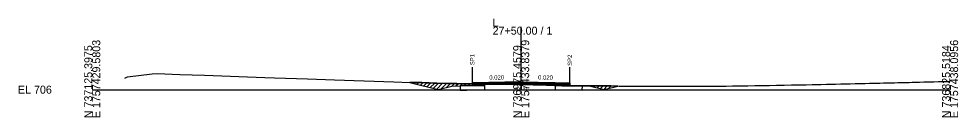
# Model space of a CAD drawing. Extents: x -26 to 4303, y -10 to 9577.
# Drawn here: x 974.3 to 1302.8, y 7490.3 to 7524.9 of the extents above; entities that cross this region are included whole.
import ezdxf

# ---------------------------------------------------------------- set-up
doc = ezdxf.new("R2010")
doc.units = 0
for name, color, linetype in [('Exist CMT Pavement', 7, 'Continuous'), ('Old_Level_2', 7, 'Continuous'), ('Pattern 1', 7, 'Continuous'), ('Prop CMT Conc Surface', 7, 'Continuous'), ('Prop CMT Concrete Structures', 7, 'Continuous'), ('Prop CMT Pvmt Course 1', 7, 'Continuous'), ('Prop CMT Pvmt Course 1 CG', 7, 'Continuous'), ('Prop CMT Pvmt Course 1 Wedge', 7, 'Continuous'), ('Prop CMT Pvmt Surface', 7, 'Continuous'), ('Prop CMT Pvmt Surface Shoulder', 7, 'Continuous'), ('Prop CMT Pvmt Wedge Surface 1', 7, 'Continuous'), ('Prop CMT Pvmt Wedge Surface 2', 7, 'Continuous'), ('Prop CMT Pvmt Wedge Surface 3', 7, 'Continuous'), ('Prop CMT Shld Paved Course 1', 7, 'Continuous'), ('Prop CMT Shld Paved Course 3', 7, 'Continuous'), ('Prop CMT Slope Grass', 7, 'Continuous'), ('Prop Road Sect_ Recs - UC Shallow (Outline)', 7, 'Continuous'), ('Prop Shade Light', 7, 'Continuous'), ('Prop XS DDE Elevations', 7, 'Continuous'), ('Prop XS SE Text', 7, 'Continuous'), ('Prop XS Shear Point Label', 7, 'Continuous'), ('Prop XS Wedging', 7, 'Continuous')]:
    doc.layers.add(name, color=color, linetype=linetype)

msp = doc.modelspace()

# ---------------------------------------------------------------- linework, layer by layer
at = {"layer": 'Exist CMT Pavement'}
for p, q in [((1133, 7502.37), (1133, 7502.03)), ((1167, 7502.37), (1167, 7501.36))]:
    msp.add_line(p, q, dxfattribs=at)
for points in [[(1150, 7502.71), (1133, 7502.37)], [(1150, 7502.71), (1167, 7502.37)]]:
    msp.add_lwpolyline(points, dxfattribs=at)
at = {"layer": 'Old_Level_2'}
for p, q in [((1150, 7500), (1150, 7522.1)), ((1150, 7500), (1150, 7522.1)), ((1000, 7500), (1150, 7500)), ((1000, 7500), (1150, 7500)), ((1150, 7500), (1300, 7500)), ((1150, 7500), (1300, 7500))]:
    msp.add_line(p, q, dxfattribs=at)
at = {"layer": 'Pattern 1'}
for p, q in [((1111.41, 7502.47), (1111.48, 7502.54)), ((1112.54, 7502.19), (1112.86, 7502.51)), ((1113.67, 7501.91), (1114.25, 7502.48)), ((1114.81, 7501.63), (1115.63, 7502.45)), ((1115.94, 7501.34), (1117, 7502.41)), ((1117.07, 7501.06), (1118.38, 7502.37)), ((1118.2, 7500.78), (1119.75, 7502.33)), ((1119.33, 7500.49), (1121.13, 7502.29)), ((1120.46, 7500.21), (1122.51, 7502.25)), ((1121.99, 7500.32), (1123.88, 7502.22)), ((1123.87, 7500.8), (1125.26, 7502.19)), ((1125.75, 7501.26), (1126.65, 7502.16)), ((1127.19, 7501.29), (1128.03, 7502.12)), ((1128.64, 7501.32), (1129.41, 7502.09)), ((1130.08, 7501.34), (1130.79, 7502.06)), ((1131.52, 7501.37), (1132.18, 7502.03)), ((1132.97, 7501.4), (1133.59, 7502.02)), ((1134.41, 7501.43), (1134.97, 7501.99)), ((1135.85, 7501.46), (1136.35, 7501.95)), ((1171.59, 7501.32), (1171.6, 7501.33)), ((1172.97, 7501.29), (1173, 7501.32)), ((1174.34, 7501.24), (1174.41, 7501.31)), ((1175.47, 7500.96), (1175.81, 7501.3)), ((1176.6, 7500.68), (1177.22, 7501.29)), ((1177.73, 7500.39), (1178.63, 7501.29)), ((1178.87, 7500.11), (1180.05, 7501.29)), ((1180.66, 7500.49), (1181.46, 7501.3)), ((1182.55, 7500.96), (1182.87, 7501.29))]:
    msp.add_line(p, q, dxfattribs=at)
for points in [[(1121, 7500.08), (1125.72, 7501.26), (1128.61, 7501.31), (1137.25, 7501.49), (1137.25, 7501.94), (1136.11, 7501.96), (1135, 7501.99), (1134.01, 7502.02), (1131.95, 7502.04), (1130.44, 7502.06), (1129.08, 7502.09), (1127.46, 7502.14), (1125.02, 7502.19), (1120.46, 7502.31), (1115.23, 7502.46), (1111.11, 7502.55)], [(1179, 7500.08), (1183.82, 7501.28), (1181.36, 7501.3), (1177.96, 7501.29), (1175.34, 7501.31), (1174.06, 7501.31), (1171.39, 7501.33), (1174.28, 7501.26)]]:
    msp.add_lwpolyline(points, close=True, dxfattribs=at)
at = {"layer": 'Prop CMT Conc Surface'}
for points in [[(1137.08, 7502.2), (1133, 7502.12)], [(1133, 7502.12), (1133, 7501.91)], [(1133, 7501.91), (1137.08, 7501.99)], [(1137.08, 7501.99), (1137.08, 7502.2)], [(1161.94, 7502.01), (1161.94, 7502.22)], [(1161.94, 7502.22), (1167, 7502.12)], [(1167, 7501.91), (1161.94, 7502.01)], [(1167, 7502.12), (1167, 7501.91)]]:
    msp.add_lwpolyline(points, dxfattribs=at)
at = {"layer": 'Prop CMT Concrete Structures'}
for points in [[(1133, 7502.12), (1133, 7502.37)], [(1137.08, 7502.2), (1133, 7502.12)], [(1150, 7502.59), (1137.08, 7502.33)], [(1137.08, 7502.33), (1137.08, 7502.2)], [(1150, 7502.59), (1161.94, 7502.35)], [(1161.94, 7502.35), (1161.94, 7502.22)], [(1161.94, 7502.22), (1167, 7502.12)], [(1167, 7502.12), (1167, 7502.37)]]:
    msp.add_lwpolyline(points, dxfattribs=at)
at = {"layer": 'Prop CMT Pvmt Course 1'}
for points in [[(1137.08, 7501.99), (1133, 7501.91)], [(1133, 7501.91), (1133, 7501.58)], [(1133, 7501.58), (1137.08, 7501.66)], [(1137.08, 7501.66), (1137.08, 7501.99)], [(1161.94, 7502.01), (1167, 7501.91)], [(1161.94, 7501.55), (1161.94, 7502.01)], [(1167, 7501.58), (1161.94, 7501.68)], [(1167, 7501.91), (1167, 7501.58)]]:
    msp.add_lwpolyline(points, dxfattribs=at)
at = {"layer": 'Prop CMT Pvmt Course 1 Wedge'}
for points in [[(1137.08, 7501.99), (1139.2, 7502.03), (1139.42, 7502.04), (1141.7, 7502.08), (1141.85, 7502.09), (1144.21, 7502.13), (1144.28, 7502.14), (1146.71, 7502.18), (1146.71, 7502.18), (1146.9, 7502.19), (1149.14, 7502.23), (1149.21, 7502.23), (1150, 7502.25)], [(1137.08, 7501.93), (1137.08, 7501.99)], [(1150, 7501.83), (1149.21, 7501.86), (1149.14, 7501.86), (1146.9, 7501.89), (1146.71, 7501.89), (1146.71, 7501.89), (1144.28, 7501.91), (1144.21, 7501.91), (1141.85, 7501.95), (1141.7, 7501.95), (1139.42, 7501.98), (1139.2, 7501.98), (1137.08, 7501.93)], [(1150, 7502.25), (1150, 7501.83)], [(1150, 7502.25), (1151.58, 7502.22), (1151.71, 7502.22), (1154.01, 7502.17), (1154.21, 7502.17), (1156.44, 7502.12), (1156.71, 7502.12), (1158.87, 7502.07), (1159.21, 7502.07), (1159.57, 7502.06), (1161.71, 7502.02), (1161.94, 7502.01)], [(1161.94, 7501.51), (1161.71, 7501.52), (1159.57, 7501.56), (1159.21, 7501.57), (1158.87, 7501.59), (1156.71, 7501.67), (1156.44, 7501.67), (1154.21, 7501.74), (1154.01, 7501.74), (1151.71, 7501.77), (1151.58, 7501.78), (1150, 7501.83)], [(1161.94, 7502.01), (1161.94, 7501.51)]]:
    msp.add_lwpolyline(points, dxfattribs=at)
at = {"layer": 'Prop CMT Pvmt Surface'}
for points in [[(1150, 7502.46), (1133, 7502.12)], [(1133, 7502.12), (1133, 7502.37)], [(1150, 7502.46), (1167, 7502.12)], [(1167, 7502.12), (1167, 7502.37)]]:
    msp.add_lwpolyline(points, dxfattribs=at)
at = {"layer": 'Prop CMT Pvmt Surface Shoulder'}
msp.add_line((1150, 7501.83), (1157.28, 7501.65), dxfattribs=at)
for points in [[(1137.09, 7501.93), (1139.2, 7501.98), (1139.42, 7501.98), (1141.7, 7501.95), (1141.85, 7501.95), (1144.21, 7501.91), (1144.28, 7501.91), (1146.71, 7501.89), (1146.71, 7501.89), (1146.9, 7501.89), (1149.14, 7501.86), (1149.21, 7501.86), (1150, 7501.83)], [(1157.28, 7501.65), (1158.87, 7501.59), (1159.21, 7501.57), (1159.57, 7501.56), (1161.71, 7501.52), (1161.94, 7501.51)]]:
    msp.add_lwpolyline(points, dxfattribs=at)
at = {"layer": 'Prop CMT Pvmt Wedge Surface 1'}
for p, q in [((1133, 7501.45), (1133, 7502.03)), ((1137.08, 7501.53), (1133, 7501.45)), ((1161.94, 7501.55), (1167, 7501.45)), ((1167, 7501.58), (1167, 7501.45))]:
    msp.add_line(p, q, dxfattribs=at)
for points in [[(1137.08, 7501.53), (1137.09, 7501.94)], [(1161.94, 7501.55), (1161.94, 7501.51)]]:
    msp.add_lwpolyline(points, dxfattribs=at)
at = {"layer": 'Prop CMT Pvmt Wedge Surface 2'}
for points in [[(1137.08, 7502.33), (1139.2, 7502.37), (1139.42, 7502.37), (1141.7, 7502.42), (1141.85, 7502.42), (1144.21, 7502.47), (1144.28, 7502.47), (1146.71, 7502.52), (1146.71, 7502.52), (1146.9, 7502.52), (1149.14, 7502.57), (1149.21, 7502.57), (1150, 7502.59)], [(1150, 7502.46), (1149.21, 7502.44), (1149.14, 7502.44), (1146.9, 7502.4), (1146.71, 7502.39), (1146.71, 7502.39), (1144.28, 7502.35), (1144.21, 7502.34), (1141.85, 7502.3), (1141.7, 7502.29), (1139.42, 7502.25), (1139.2, 7502.24), (1137.08, 7502.2)], [(1137.08, 7501.94), (1137.08, 7502.33)], [(1150, 7502.59), (1150, 7502.46)], [(1150, 7502.59), (1151.58, 7502.55), (1151.71, 7502.55), (1154.01, 7502.5), (1154.21, 7502.5), (1156.44, 7502.46), (1156.71, 7502.45), (1158.87, 7502.41), (1159.21, 7502.4), (1159.57, 7502.39), (1161.71, 7502.35), (1161.94, 7502.35)], [(1161.94, 7502.22), (1161.71, 7502.23), (1159.57, 7502.27), (1159.21, 7502.28), (1158.87, 7502.28), (1156.71, 7502.33), (1156.44, 7502.33), (1154.21, 7502.38), (1154.01, 7502.38), (1151.71, 7502.43), (1151.58, 7502.43), (1150, 7502.46)], [(1161.94, 7502.35), (1161.94, 7501.51)]]:
    msp.add_lwpolyline(points, dxfattribs=at)
at = {"layer": 'Prop CMT Pvmt Wedge Surface 3'}
for points in [[(1137.08, 7502.2), (1139.2, 7502.24), (1139.42, 7502.25), (1141.7, 7502.29), (1141.85, 7502.3), (1144.21, 7502.34), (1144.28, 7502.35), (1146.71, 7502.39), (1146.71, 7502.39), (1146.9, 7502.4), (1149.14, 7502.44), (1149.21, 7502.44), (1150, 7502.46)], [(1150, 7502.25), (1149.21, 7502.24), (1149.14, 7502.23), (1146.9, 7502.19), (1146.71, 7502.19), (1146.71, 7502.19), (1144.28, 7502.14), (1144.21, 7502.14), (1141.85, 7502.09), (1141.7, 7502.09), (1139.42, 7502.04), (1139.2, 7502.04), (1137.08, 7501.99)], [(1137.08, 7501.99), (1137.08, 7502.2)], [(1150, 7502.46), (1150, 7502.25)], [(1150, 7502.46), (1151.58, 7502.43), (1151.71, 7502.43), (1154.01, 7502.38), (1154.21, 7502.38), (1156.44, 7502.33), (1156.71, 7502.33), (1158.87, 7502.28), (1159.21, 7502.28), (1159.57, 7502.27), (1161.71, 7502.23), (1161.94, 7502.22)], [(1161.94, 7502.01), (1161.71, 7502.02), (1159.57, 7502.06), (1159.21, 7502.07), (1158.87, 7502.07), (1156.71, 7502.12), (1156.44, 7502.12), (1154.21, 7502.17), (1154.01, 7502.17), (1151.71, 7502.22), (1151.58, 7502.22), (1150, 7502.25)], [(1161.94, 7502.22), (1161.94, 7502.01)]]:
    msp.add_lwpolyline(points, dxfattribs=at)
at = {"layer": 'Prop CMT Shld Paved Course 1'}
for points in [[(1133, 7501.91), (1133, 7502.37)], [(1150, 7502.25), (1133, 7501.91)], [(1150, 7502.25), (1167, 7501.91)], [(1167, 7501.91), (1167, 7502.37)]]:
    msp.add_lwpolyline(points, dxfattribs=at)
at = {"layer": 'Prop CMT Shld Paved Course 3'}
for points in [[(1150, 7502.71), (1133, 7502.37)], [(1133, 7502.37), (1133, 7502.12)], [(1133, 7502.12), (1137.08, 7502.2)], [(1137.08, 7502.33), (1150, 7502.59)], [(1137.08, 7502.2), (1137.08, 7502.33)], [(1150, 7502.71), (1167, 7502.37)], [(1161.94, 7502.35), (1150, 7502.59)], [(1161.94, 7502.22), (1161.94, 7502.35)], [(1167, 7502.12), (1161.94, 7502.22)], [(1167, 7502.37), (1167, 7502.12)]]:
    msp.add_lwpolyline(points, dxfattribs=at)
at = {"layer": 'Prop CMT Slope Grass'}
msp.add_lwpolyline([(1011.35, 7504.04), (1012.37, 7504.5), (1020.98, 7505.54), (1022.65, 7505.65), (1030.67, 7505.36), (1039.2, 7505.06), (1060.32, 7504.3), (1063.69, 7504.18), (1075.33, 7503.79), (1084.67, 7503.45), (1105.5, 7502.75), (1111.17, 7502.55), (1114.7, 7502.48), (1116.69, 7502.41), (1117.53, 7502.39), (1119.2, 7502.34), (1119.96, 7502.32), (1121.7, 7502.27), (1122.39, 7502.26), (1124.2, 7502.21), (1126.11, 7502.17), (1126.7, 7502.16), (1127.26, 7502.15), (1129.2, 7502.09), (1131.26, 7502.05), (1131.7, 7502.04), (1132.12, 7502.04), (1134.2, 7502.02), (1134.55, 7502.01), (1136.98, 7501.93), (1139.2, 7501.98), (1141.85, 7501.95), (1144.28, 7501.91), (1146.9, 7501.89), (1149.21, 7501.86), (1150, 7501.83), (1151.71, 7501.77), (1154.21, 7501.74), (1156.71, 7501.67), (1158.87, 7501.59), (1159.21, 7501.57), (1159.57, 7501.56), (1161.71, 7501.52), (1162.15, 7501.5), (1164.21, 7501.36), (1164.72, 7501.36), (1166.71, 7501.36), (1167.29, 7501.35), (1169.22, 7501.34), (1169.87, 7501.34), (1171.72, 7501.32), (1172.44, 7501.32), (1174.22, 7501.31), (1175.02, 7501.31), (1176.72, 7501.29), (1177.59, 7501.29), (1179.22, 7501.29), (1180.16, 7501.29), (1181.72, 7501.3), (1182.74, 7501.3), (1184.22, 7501.28), (1185.62, 7501.26), (1186.72, 7501.26), (1187.89, 7501.26), (1189.22, 7501.25), (1190.46, 7501.25), (1191.72, 7501.24), (1193.03, 7501.23), (1194.23, 7501.22), (1195.61, 7501.21), (1196.73, 7501.21), (1198.18, 7501.21), (1199.23, 7501.22), (1200.76, 7501.21), (1201.73, 7501.22), (1203.33, 7501.23), (1204.23, 7501.22), (1205.91, 7501.22), (1206.73, 7501.24), (1208.48, 7501.2), (1209.23, 7501.19), (1209.94, 7501.2), (1211.73, 7501.22), (1213.63, 7501.23), (1214.23, 7501.23), (1216.2, 7501.23), (1216.73, 7501.23), (1218.78, 7501.23), (1219.24, 7501.24), (1221.35, 7501.26), (1221.74, 7501.26), (1223.92, 7501.29), (1224.24, 7501.29), (1226.74, 7501.34), (1229.24, 7501.36), (1231.74, 7501.41), (1234.24, 7501.43), (1234.98, 7501.45), (1236.79, 7501.49), (1239.24, 7501.54), (1241.94, 7501.58), (1244.52, 7501.64), (1246.75, 7501.68), (1247.09, 7501.68), (1249.25, 7501.73), (1249.66, 7501.74), (1251.75, 7501.8), (1252.24, 7501.81), (1254.25, 7501.82), (1254.81, 7501.83), (1256.75, 7501.9), (1257.39, 7501.91), (1259.25, 7501.95), (1259.96, 7501.96), (1261.75, 7502.01), (1262.54, 7502.02), (1264.25, 7502.06), (1265.11, 7502.08), (1266.75, 7502.12), (1268.31, 7502.15), (1269.26, 7502.17), (1270.26, 7502.2), (1271.76, 7502.23), (1272.83, 7502.25), (1274.26, 7502.29), (1275.41, 7502.32), (1276.76, 7502.35), (1277.98, 7502.39), (1279.26, 7502.41), (1280.55, 7502.44), (1281.76, 7502.48), (1283.13, 7502.52), (1284.26, 7502.54), (1285.7, 7502.57), (1286.76, 7502.6), (1288.28, 7502.64), (1289.26, 7502.67), (1290.85, 7502.71), (1291.77, 7502.73), (1293.42, 7502.77), (1294.27, 7502.79), (1296, 7502.84), (1296.77, 7502.86), (1298.57, 7502.91), (1299.27, 7502.92), (1300, 7502.94)], dxfattribs=at)
at = {"layer": 'Prop Road Sect_ Recs - UC Shallow (Outline)'}
for points in [[(1129.61, 7501.33), (1128.61, 7501.31), (1128.64, 7499.81), (1137.25, 7499.99), (1137.25, 7501.49)], [(1161.94, 7500), (1171.36, 7499.81), (1171.39, 7501.31), (1171.39, 7501.33), (1170.39, 7501.34), (1169.37, 7501.34), (1168.37, 7501.35), (1167.19, 7501.35), (1164.27, 7501.36), (1163.88, 7501.38), (1163.31, 7501.42), (1162.34, 7501.48), (1161.94, 7501.5)]]:
    msp.add_lwpolyline(points, close=True, dxfattribs=at)
at = {"layer": 'Prop Shade Light'}
for p, q in [((1130.16, 7501.35), (1128.61, 7501.31)), ((1128.61, 7501.31), (1128.64, 7499.81)), ((1137.25, 7499.99), (1137.25, 7501.49)), ((1164.21, 7501.36), (1161.94, 7501.5)), ((1161.94, 7501.5), (1161.94, 7500)), ((1164.98, 7501.35), (1164.21, 7501.36)), ((1166.57, 7501.35), (1164.98, 7501.35)), ((1168.22, 7501.35), (1166.57, 7501.35)), ((1128.64, 7499.81), (1130.99, 7499.86)), ((1130.99, 7499.86), (1137.25, 7499.99)), ((1161.94, 7500), (1171.36, 7499.81))]:
    msp.add_line(p, q, dxfattribs=at)
for points in [[(1137.25, 7501.49), (1130.18, 7501.35), (1130.16, 7501.35)], [(1171.36, 7499.81), (1171.39, 7501.33), (1169.41, 7501.34), (1169.15, 7501.34), (1168.22, 7501.35)]]:
    msp.add_lwpolyline(points, dxfattribs=at)
at = {"layer": 'Prop XS DDE Elevations'}
for points in [[(1133, 7502.03), (1134.2, 7502.02), (1134.55, 7502.01), (1136.98, 7501.93), (1137.09, 7501.94), (1137.08, 7501.53), (1133, 7501.45)], [(1139.2, 7501.98), (1141.85, 7501.95), (1141.7, 7501.95), (1139.42, 7501.98)], [(1144.28, 7501.91), (1146.71, 7501.89), (1146.9, 7501.89)], [(1150, 7501.83), (1151.71, 7501.77), (1152.79, 7501.76)], [(1152.79, 7501.76), (1157.28, 7501.65), (1156.71, 7501.67), (1154.21, 7501.74)], [(1164.72, 7501.36), (1166.71, 7501.36), (1167, 7501.36), (1167, 7501.45), (1161.94, 7501.55), (1161.94, 7501.51), (1162.15, 7501.5), (1164.21, 7501.36)]]:
    msp.add_lwpolyline(points, close=True, dxfattribs=at)
at = {"layer": 'Prop XS Shear Point Label'}
for p, q in [((1133, 7502.37), (1133, 7507.84)), ((1167, 7502.37), (1167, 7507.84))]:
    msp.add_line(p, q, dxfattribs=at)
at = {"layer": 'Prop XS Wedging'}
for p, q in [((1150, 7502.59), (1137.08, 7502.33)), ((1137.08, 7502.2), (1150, 7502.46)), ((1137.08, 7502.33), (1137.08, 7502.2)), ((1137.08, 7502.2), (1137.08, 7501.99)), ((1137.08, 7501.99), (1137.08, 7501.94)), ((1137.09, 7502.2), (1150, 7502.46)), ((1149.32, 7502.11), (1149.07, 7501.86)), ((1149.07, 7501.86), (1149.32, 7502.11)), ((1149.32, 7502.11), (1149.07, 7501.86)), ((1149.32, 7502.11), (1150.01, 7502.13)), ((1149.32, 7502.11), (1149.99, 7502.13)), ((1161.94, 7501.89), (1149.99, 7502.13)), ((1149.99, 7502.13), (1150, 7502.13)), ((1161.94, 7502.35), (1150, 7502.59)), ((1161.93, 7502.22), (1150, 7502.46)), ((1150, 7502.13), (1150.01, 7502.13)), ((1150.01, 7502.13), (1161.94, 7501.89)), ((1161.94, 7502.22), (1161.94, 7502.35)), ((1161.94, 7502.01), (1161.94, 7502.22)), ((1161.94, 7501.89), (1161.94, 7502.01)), ((1161.94, 7501.51), (1161.94, 7501.55))]:
    msp.add_line(p, q, dxfattribs=at)
for points in [[(1150, 7502.46), (1150, 7502.46), (1137.08, 7502.2)], [(1137.08, 7501.94), (1137.09, 7501.94), (1137.09, 7501.93)], [(1137.09, 7501.93), (1139.2, 7501.98), (1141.85, 7501.95), (1144.28, 7501.91), (1146.9, 7501.89), (1149.07, 7501.86)], [(1149.07, 7501.86), (1149.21, 7501.86), (1150, 7501.83), (1151.71, 7501.77), (1154.21, 7501.74), (1156.71, 7501.67), (1158.87, 7501.59), (1159.21, 7501.57), (1159.57, 7501.56), (1161.71, 7501.52), (1161.94, 7501.51)], [(1150, 7502.13), (1149.99, 7502.13), (1149.32, 7502.11)], [(1149.99, 7502.13), (1149.99, 7502.13)], [(1161.94, 7502.22), (1150, 7502.46), (1150, 7502.46)], [(1150, 7502.46), (1150, 7502.46), (1161.94, 7502.22)], [(1161.94, 7501.89), (1150.01, 7502.13), (1150, 7502.13)], [(1150.01, 7502.13), (1150.01, 7502.13)], [(1161.94, 7501.55), (1161.94, 7501.68), (1161.94, 7501.89)], [(1161.94, 7501.51), (1161.94, 7501.51)]]:
    msp.add_lwpolyline(points, dxfattribs=at)

# ---------------------------------------------------------------- texts
at = {"layer": 'Old_Level_2'}
for s, p in [('L', (1140, 7522.1)), ('L', (1140, 7522.1)), ('27+50.00 / 1', (1140, 7519.3)), ('27+50.00 / 1', (1140, 7519.3)), ('EL 706', (974, 7498.6)), ('EL 706', (974, 7498.6))]:
    msp.add_text(s, height=2.8, dxfattribs=at).set_placement(p)
for s, p in [('E 1757429.5803', (1002.8, 7490)), ('E 1757429.5803', (1002.8, 7490)), ('E 1757433.8379', (1152.8, 7490)), ('E 1757433.8379', (1152.8, 7490)), ('E 1757438.0956', (1302.8, 7490)), ('E 1757438.0956', (1302.8, 7490)), ('N 737125.3975', (1000, 7490)), ('N 737125.3975', (1000, 7490)), ('N 736975.4579', (1150, 7490)), ('N 736975.4579', (1150, 7490)), ('N 736825.5184', (1300, 7490)), ('N 736825.5184', (1300, 7490))]:
    msp.add_text(s, height=2.8, rotation=90, dxfattribs=at).set_placement(p)
at = {"layer": 'Prop CMT Pvmt Course 1 CG'}
msp.add_text('707.83', height=1, dxfattribs=at).set_placement((1147.88, 7499.83))
at = {"layer": 'Prop XS SE Text'}
for rotation, p in [(1.1458, (1138.86, 7503.49)), (358.8542, (1155.9, 7503.59))]:
    msp.add_text('0.020', height=1.5, rotation=rotation, dxfattribs=at).set_placement(p)
at = {"layer": 'Prop XS Shear Point Label'}
for s, p in [('SP1', (1133.64, 7508.59)), ('SP2', (1167.76, 7508.37))]:
    msp.add_text(s, height=1.5, rotation=90, dxfattribs=at).set_placement(p)

doc.saveas('drawing.dxf')
